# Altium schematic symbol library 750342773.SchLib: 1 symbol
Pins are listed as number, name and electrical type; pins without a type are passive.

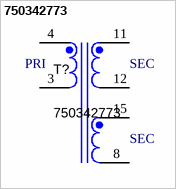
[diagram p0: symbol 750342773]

## 750342773
designator T?
TRANSFORMER,  80.0uH, 10%, TH; Manufacturer: Wurth Elektronics; SymbolCreator: x0199378
pins: 3, 4, 8, 11, 12, 15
